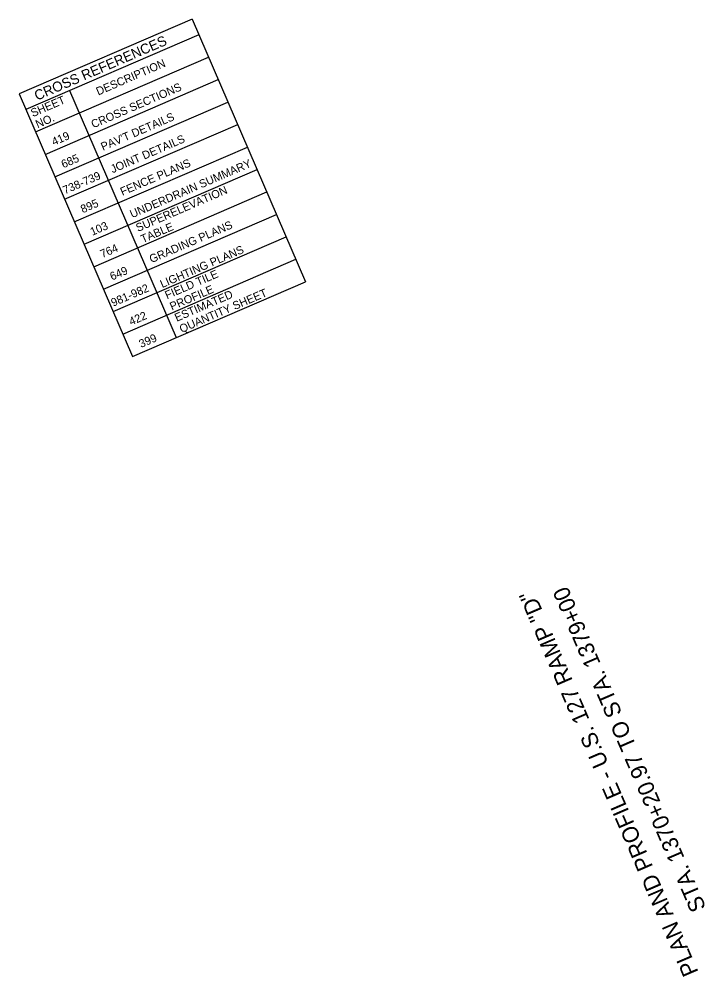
# Model space of a CAD drawing. Extents: x -52111063 to 1398117, y -51712923 to 573526.
# Drawn here: x 1397588 to 1398117, y 572789 to 573526 of the extents above; entities that cross this region are included whole.
import ezdxf

# ---------------------------------------------------------------- set-up
doc = ezdxf.new("R2010")
doc.units = 0
doc.layers.add('Level 1', color=7, linetype='Continuous')
doc.layers.add('Level 40', color=7, linetype='Continuous')

msp = doc.modelspace()

# ---------------------------------------------------------------- linework, layer by layer
at = {"layer": 'Level 40'}
for p, q in [((1397721.21, 573526.18), (1397587.95, 573468.66)), ((1397721.21, 573526.18), (1397808.47, 573324.03)), ((1397726.37, 573514.24), (1397593.11, 573456.71)), ((1397600.57, 573439.42), (1397733.83, 573496.94)), ((1397608.04, 573422.13), (1397741.29, 573479.65)), ((1397587.95, 573468.66), (1397675.21, 573266.51)), ((1397626.82, 573471.26), (1397708.92, 573281.06)), ((1397615.5, 573404.84), (1397748.76, 573462.36)), ((1397622.96, 573387.55), (1397756.22, 573445.07)), ((1397630.43, 573370.26), (1397763.69, 573427.78)), ((1397637.89, 573352.97), (1397771.15, 573410.49)), ((1397645.35, 573335.67), (1397778.61, 573393.2)), ((1397652.82, 573318.38), (1397786.08, 573375.91)), ((1397660.28, 573301.09), (1397793.54, 573358.62)), ((1397667.75, 573283.8), (1397801.01, 573341.32)), ((1397675.21, 573266.51), (1397808.47, 573324.03))]:
    msp.add_line(p, q, dxfattribs=at)

# ---------------------------------------------------------------- texts
at = {"layer": 'Level 1'}
for s, p in [('PLAN AND PROFILE - U.S. 127 RAMP "D"', (1398111.25, 572792.75)), ('STA. 1370+20.97 TO STA. 1379+00', (1398117.12, 572842.23))]:
    msp.add_text(s, height=12.5, rotation=113.34806, dxfattribs=at).set_placement(p)
at = {"layer": 'Level 40'}
for s, height, p in [('CROSS REFERENCES', 7.6923, (1397601.71, 573463.32)), ('DESCRIPTION', 6.25, (1397648.84, 573467.35)), ('CROSS SECTIONS  ', 6.25, (1397645.03, 573442.09)), ('SHEET ', 6.25, (1397598.51, 573450.72)), ('NO.', 6.25, (1397602.22, 573442.12)), ("PAV'T DETAILS   ", 6.25, (1397652.49, 573424.8)), (' 419', 6.25, (1397612.55, 573427.75)), ('JOINT DETAILS   ', 6.25, (1397659.95, 573407.51)), (' 685', 6.25, (1397619.86, 573410.39)), ('FENCE PLANS     ', 6.25, (1397667.42, 573390.21)), ('UNDERDRAIN SUMMARY', 6.25, (1397674.88, 573372.92)), ('738-739', 6.25, (1397623.21, 573391.32)), ('SUPERELEVATION  ', 6.25, (1397679.44, 573362.37)), (' 895', 6.25, (1397634.78, 573375.8)), (' 103', 6.25, (1397642.11, 573358.45)), ('TABLE           ', 6.25, (1397683.17, 573353.72)), ('GRADING PLANS   ', 6.25, (1397689.81, 573338.34)), (' 764', 6.25, (1397649.87, 573341.29)), ('LIGHTING PLANS', 6.25, (1397698.1, 573319.14)), (' 649', 6.25, (1397657.33, 573324)), ('FIELD TILE       ', 6.25, (1397701.83, 573310.5)), ('981-982', 6.25, (1397660.33, 573304.78)), ('PROFILE  ', 6.25, (1397705.56, 573301.85)), ('QUANTITY SHEET  ', 6.25, (1397713.03, 573284.56)), ('ESTIMATED       ', 6.25, (1397709.3, 573293.2)), (' 422', 6.25, (1397672.01, 573289.31)), (' 399', 6.25, (1397679.72, 573272.13))]:
    msp.add_text(s, height=height, rotation=23.34806, dxfattribs=at).set_placement(p)

doc.saveas('drawing.dxf')
